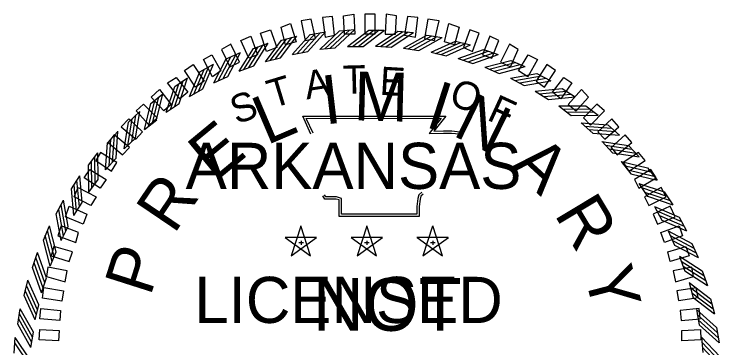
# Model space of a CAD drawing. Extents: x 16 to 1228743, y 11 to 152440.
# Drawn here: x 17.6797 to 17.8514, y 10.9098 to 10.9908 of the extents above; entities that cross this region are included whole.
import ezdxf

# ---------------------------------------------------------------- set-up
doc = ezdxf.new("R2010")
doc.units = 0
doc.layers.add('STAMP_JUSTIN', color=7, linetype='Continuous')
doc.layers.add('STAMP_PRELIM', color=7, linetype='Continuous')

msp = doc.modelspace()

# ---------------------------------------------------------------- linework, layer by layer
at = {"layer": 'STAMP_JUSTIN'}
for p, q in [((17.75872, 10.98673), (17.76248, 10.98708)), ((17.74471, 10.98447), (17.74835, 10.98543)), ((17.75167, 10.98589), (17.75538, 10.98654)), ((17.76586, 10.98694), (17.76963, 10.98694)), ((17.77292, 10.98666), (17.77668, 10.98638)), ((17.77997, 10.98574), (17.7837, 10.98516)), ((17.73788, 10.98247), (17.74144, 10.98373)), ((17.78692, 10.98425), (17.79058, 10.98336)), ((17.75397, 10.98227), (17.75773, 10.98261)), ((17.76072, 10.98293), (17.7645, 10.98293)), ((17.7675, 10.98304), (17.77127, 10.98276)), ((17.77427, 10.98258), (17.778, 10.98199)), ((17.79372, 10.98219), (17.7973, 10.981)), ((17.73125, 10.97992), (17.73469, 10.98147)), ((17.74075, 10.97928), (17.74441, 10.98024)), ((17.7473, 10.98105), (17.75102, 10.9817)), ((17.78097, 10.98157), (17.78464, 10.98068)), ((17.72485, 10.97684), (17.72815, 10.97866)), ((17.78757, 10.98001), (17.79116, 10.97881)), ((17.80033, 10.97957), (17.80379, 10.97809)), ((17.73437, 10.97698), (17.73793, 10.97824)), ((17.79402, 10.97791), (17.79749, 10.97642)), ((17.71873, 10.97323), (17.72186, 10.97532)), ((17.7282, 10.97416), (17.73165, 10.97571)), ((17.80027, 10.97528), (17.80361, 10.97351)), ((17.8067, 10.97642), (17.81003, 10.97465)), ((17.72229, 10.97084), (17.7256, 10.97266)), ((17.80629, 10.97214), (17.80947, 10.97011)), ((17.81278, 10.97275), (17.81596, 10.97072)), ((17.71292, 10.96913), (17.71588, 10.97147)), ((17.71667, 10.96704), (17.71982, 10.96913)), ((17.81202, 10.96852), (17.81502, 10.96623)), ((17.81854, 10.96859), (17.82154, 10.9663)), ((17.70748, 10.96456), (17.71023, 10.96714)), ((17.71139, 10.96279), (17.71435, 10.96514)), ((17.81744, 10.96444), (17.82024, 10.96191)), ((17.82394, 10.96397), (17.82674, 10.96144)), ((17.70243, 10.95957), (17.70495, 10.96236)), ((17.70647, 10.95812), (17.70923, 10.9607)), ((17.8225, 10.95993), (17.82508, 10.95717)), ((17.82894, 10.95892), (17.83152, 10.95617)), ((17.69781, 10.95417), (17.70009, 10.95716)), ((17.70195, 10.95306), (17.70449, 10.95586)), ((17.82717, 10.95501), (17.82952, 10.95205)), ((17.83351, 10.95347), (17.83585, 10.95052)), ((17.69365, 10.9484), (17.69568, 10.95158)), ((17.69787, 10.94764), (17.70017, 10.95065)), ((17.83142, 10.94972), (17.83351, 10.94658)), ((17.83761, 10.94767), (17.8397, 10.94453)), ((17.68998, 10.94232), (17.69174, 10.94565)), ((17.69425, 10.94191), (17.69629, 10.94509)), ((17.83521, 10.94411), (17.83704, 10.9408)), ((17.84121, 10.94155), (17.84304, 10.93825)), ((17.68683, 10.93595), (17.68831, 10.93942)), ((17.69112, 10.93589), (17.69289, 10.93923)), ((17.74939, 10.93938), (17.74703, 10.93214)), ((17.75174, 10.93215), (17.74939, 10.93939)), ((17.76538, 10.93938), (17.76302, 10.93214)), ((17.76773, 10.93215), (17.76539, 10.93939)), ((17.78137, 10.93938), (17.77901, 10.93214)), ((17.78372, 10.93215), (17.78138, 10.93939)), ((17.83853, 10.93819), (17.84008, 10.93475)), ((17.75319, 10.93661), (17.74558, 10.93662)), ((17.74559, 10.93661), (17.75174, 10.93214)), ((17.74704, 10.93215), (17.7532, 10.93661)), ((17.7494, 10.93581), (17.7494, 10.93485)), ((17.76918, 10.93661), (17.76157, 10.93662)), ((17.76158, 10.93661), (17.76773, 10.93214)), ((17.76303, 10.93215), (17.76919, 10.93661)), ((17.76539, 10.93581), (17.76539, 10.93485)), ((17.78517, 10.93661), (17.77756, 10.93662)), ((17.77757, 10.93661), (17.78372, 10.93214)), ((17.77902, 10.93215), (17.78518, 10.93661)), ((17.78138, 10.93581), (17.78138, 10.93485)), ((17.74885, 10.9354), (17.74998, 10.9354)), ((17.76484, 10.9354), (17.76597, 10.9354)), ((17.78083, 10.9354), (17.78196, 10.9354)), ((17.8443, 10.93515), (17.84585, 10.93171)), ((17.68421, 10.92934), (17.6854, 10.93292)), ((17.68849, 10.92964), (17.68998, 10.93312)), ((17.84135, 10.93202), (17.84261, 10.92846)), ((17.84685, 10.92851), (17.84811, 10.92496)), ((17.68215, 10.92254), (17.68304, 10.9262)), ((17.68639, 10.92319), (17.68758, 10.92678)), ((17.84366, 10.92565), (17.84462, 10.92199)), ((17.68483, 10.91659), (17.68572, 10.92027)), ((17.84884, 10.92169), (17.8498, 10.91805)), ((17.68065, 10.91559), (17.68124, 10.91932)), ((17.84542, 10.9191), (17.84608, 10.91538)), ((17.68381, 10.90989), (17.6844, 10.91362)), ((17.85027, 10.91473), (17.85092, 10.91102)), ((17.67974, 10.90855), (17.68001, 10.91231)), ((17.84664, 10.91243), (17.84699, 10.90866))]:
    msp.add_line(p, q, dxfattribs=at)
for points in [[(17.75773, 10.98261), (17.76248, 10.98708)], [(17.7444, 10.98024), (17.74835, 10.98543)], [(17.74729, 10.98104), (17.75166, 10.98588)], [(17.74849, 10.98124), (17.75286, 10.98608)], [(17.74978, 10.9815), (17.75415, 10.98634)], [(17.75102, 10.9817), (17.75538, 10.98655)], [(17.75397, 10.98226), (17.75872, 10.98673)], [(17.75517, 10.98236), (17.75993, 10.98683)], [(17.75648, 10.98251), (17.76123, 10.98698)], [(17.76071, 10.98293), (17.76586, 10.98694)], [(17.76193, 10.98292), (17.76707, 10.98693)], [(17.76324, 10.98295), (17.76838, 10.98696)], [(17.76449, 10.98293), (17.76964, 10.98695)], [(17.76749, 10.98303), (17.77292, 10.98666)], [(17.7687, 10.98293), (17.77413, 10.98656)], [(17.77001, 10.98287), (17.77544, 10.98649)], [(17.77126, 10.98276), (17.77669, 10.98639)], [(17.77426, 10.98258), (17.77997, 10.98574)], [(17.77546, 10.98238), (17.78116, 10.98554)], [(17.77676, 10.9822), (17.78246, 10.98537)], [(17.73793, 10.97824), (17.74144, 10.98373)], [(17.74075, 10.97927), (17.7447, 10.98446)], [(17.74192, 10.97957), (17.74588, 10.98476)], [(17.74318, 10.97993), (17.74714, 10.98512)], [(17.778, 10.982), (17.7837, 10.98516)], [(17.78097, 10.98157), (17.78691, 10.98425)], [(17.78214, 10.98127), (17.78809, 10.98395)], [(17.78342, 10.98099), (17.78937, 10.98367)], [(17.73437, 10.97697), (17.73788, 10.98247)], [(17.73552, 10.97737), (17.73903, 10.98286)], [(17.73674, 10.97783), (17.74025, 10.98333)], [(17.78464, 10.98068), (17.79059, 10.98336)], [(17.78757, 10.98001), (17.79371, 10.98219)], [(17.72931, 10.97464), (17.73236, 10.98041)], [(17.7305, 10.9752), (17.73354, 10.98097)], [(17.73165, 10.97571), (17.73469, 10.98147)], [(17.78871, 10.97961), (17.79486, 10.98179)], [(17.78997, 10.97923), (17.79611, 10.98141)], [(17.79115, 10.97882), (17.7973, 10.981)], [(17.72559, 10.97266), (17.72815, 10.97866)], [(17.7282, 10.97415), (17.73125, 10.97992)], [(17.79401, 10.9779), (17.80032, 10.97957)], [(17.79513, 10.97742), (17.80143, 10.97908)], [(17.79634, 10.97693), (17.80265, 10.97859)], [(17.72229, 10.97083), (17.72485, 10.97683)], [(17.72336, 10.97141), (17.72592, 10.97741)], [(17.72449, 10.97207), (17.72705, 10.97807)], [(17.79749, 10.97642), (17.8038, 10.97809)], [(17.71981, 10.96913), (17.72187, 10.97532)], [(17.80027, 10.97528), (17.80669, 10.97642)], [(17.80133, 10.9747), (17.80776, 10.97584)], [(17.8025, 10.97411), (17.80893, 10.97525)], [(17.71769, 10.9677), (17.71974, 10.97389)], [(17.71876, 10.96845), (17.72081, 10.97464)], [(17.80361, 10.97352), (17.81003, 10.97466)], [(17.71667, 10.96703), (17.71873, 10.97322)], [(17.80628, 10.97214), (17.81278, 10.97275)], [(17.8073, 10.97148), (17.81379, 10.97209)], [(17.71234, 10.96353), (17.71388, 10.96987)], [(17.71335, 10.96437), (17.71489, 10.97071)], [(17.71434, 10.96514), (17.71588, 10.97148)], [(17.80841, 10.9708), (17.81491, 10.9714)], [(17.80947, 10.97011), (17.81596, 10.97072)], [(17.71138, 10.96278), (17.71292, 10.96912)], [(17.81201, 10.96852), (17.81854, 10.96859)], [(17.70922, 10.9607), (17.71023, 10.96715)], [(17.81297, 10.96778), (17.81949, 10.96785)], [(17.81403, 10.96701), (17.82055, 10.96707)], [(17.70736, 10.95894), (17.70837, 10.96538)], [(17.7083, 10.95985), (17.7093, 10.9663)], [(17.75182, 10.96171), (17.74981, 10.96606), (17.78458, 10.96608), (17.78167, 10.96243), (17.78403, 10.96246), (17.78601, 10.96249), (17.78798, 10.96227)], [(17.75232, 10.96194), (17.75067, 10.96551), (17.78343, 10.96553), (17.78052, 10.96187), (17.78404, 10.96191), (17.78598, 10.96194), (17.78792, 10.96173)], [(17.81502, 10.96624), (17.82154, 10.9663)], [(17.70647, 10.95811), (17.70748, 10.96456)], [(17.81743, 10.96444), (17.82394, 10.96397)], [(17.81832, 10.96362), (17.82483, 10.96315)], [(17.70363, 10.95494), (17.7041, 10.96144)], [(17.70448, 10.95586), (17.70495, 10.96237)], [(17.81931, 10.96277), (17.82582, 10.96229)], [(17.82024, 10.96191), (17.82674, 10.96144)], [(17.70195, 10.95305), (17.70243, 10.95956)], [(17.70278, 10.95395), (17.70325, 10.96045)], [(17.82249, 10.95993), (17.82894, 10.95892)], [(17.82331, 10.95904), (17.82976, 10.95803)], [(17.82423, 10.9581), (17.83067, 10.95709)], [(17.69939, 10.94965), (17.69932, 10.95618)], [(17.70016, 10.95064), (17.70009, 10.95717)], [(17.82508, 10.95718), (17.83153, 10.95617)], [(17.69862, 10.94859), (17.69855, 10.95512)], [(17.82716, 10.95501), (17.8335, 10.95348)], [(17.69787, 10.94764), (17.69781, 10.95416)], [(17.82791, 10.95405), (17.83425, 10.95252)], [(17.82874, 10.95305), (17.83508, 10.95151)], [(17.69628, 10.94509), (17.69568, 10.95158)], [(17.82951, 10.95206), (17.83585, 10.95052)], [(17.69492, 10.94292), (17.69431, 10.94941)], [(17.6956, 10.94404), (17.69499, 10.95053)], [(17.83141, 10.94973), (17.8376, 10.94767)], [(17.69425, 10.9419), (17.69365, 10.9484)], [(17.77875, 10.94757), (17.77802, 10.94697), (17.77777, 10.94604), (17.77756, 10.94416), (17.77756, 10.94228), (17.75925, 10.94228), (17.75925, 10.94498), (17.75925, 10.9461), (17.758, 10.94649), (17.75545, 10.94649), (17.75512, 10.94699)], [(17.83207, 10.94871), (17.83826, 10.94666)], [(17.83282, 10.94764), (17.83902, 10.94558)], [(17.7791, 10.94714), (17.77851, 10.94666), (17.77831, 10.94594), (17.77811, 10.94413), (17.77811, 10.94173), (17.7587, 10.94173), (17.7587, 10.94498), (17.7587, 10.9457), (17.75792, 10.94594), (17.75515, 10.94594), (17.75466, 10.94669)], [(17.83351, 10.94659), (17.8397, 10.94453)], [(17.69228, 10.93813), (17.69114, 10.94455)], [(17.69288, 10.93923), (17.69174, 10.94565)], [(17.83521, 10.94411), (17.84121, 10.94155)], [(17.6917, 10.93696), (17.69056, 10.94338)], [(17.83579, 10.94304), (17.84179, 10.94048)], [(17.69112, 10.93589), (17.68998, 10.94231)], [(17.83644, 10.94191), (17.84244, 10.93935)], [(17.83704, 10.9408), (17.84304, 10.93825)], [(17.68997, 10.93311), (17.68831, 10.93942)], [(17.68947, 10.93196), (17.6878, 10.93827)], [(17.83853, 10.9382), (17.8443, 10.93515)], [(17.68849, 10.92964), (17.68683, 10.93594)], [(17.68898, 10.93075), (17.68731, 10.93705)], [(17.83902, 10.93708), (17.84478, 10.93404)], [(17.83958, 10.9359), (17.84535, 10.93286)], [(17.84008, 10.93475), (17.84585, 10.93171)], [(17.68758, 10.92678), (17.6854, 10.93292)], [(17.68678, 10.92434), (17.6846, 10.93048)], [(17.68717, 10.92559), (17.68499, 10.93174)], [(17.84135, 10.93203), (17.84685, 10.92852)], [(17.84174, 10.93088), (17.84724, 10.92737)], [(17.68639, 10.92319), (17.68421, 10.92934)], [(17.84221, 10.92966), (17.8477, 10.92614)], [(17.84262, 10.92847), (17.84811, 10.92496)], [(17.68572, 10.92026), (17.68304, 10.92621)], [(17.84365, 10.92565), (17.84884, 10.9217)], [(17.68513, 10.91777), (17.68245, 10.92371)], [(17.68541, 10.91904), (17.68273, 10.92499)], [(17.84395, 10.92447), (17.84914, 10.92052)], [(17.68483, 10.91659), (17.68215, 10.92254)], [(17.84431, 10.92321), (17.8495, 10.91926)], [(17.84462, 10.922), (17.84981, 10.91804)], [(17.6844, 10.91362), (17.68124, 10.91932)], [(17.84542, 10.9191), (17.85026, 10.91473)], [(17.68402, 10.91108), (17.68085, 10.91679)], [(17.68419, 10.91238), (17.68103, 10.91808)], [(17.84562, 10.91791), (17.85046, 10.91354)], [(17.68382, 10.90988), (17.68065, 10.91559)], [(17.84587, 10.91662), (17.85072, 10.91225)], [(17.84608, 10.91538), (17.85093, 10.91101)], [(17.68363, 10.90689), (17.68001, 10.91231)], [(17.84664, 10.91243), (17.85111, 10.90768)], [(17.68353, 10.90563), (17.67991, 10.91106)], [(17.84674, 10.91122), (17.85121, 10.90647)], [(17.84689, 10.90992), (17.85136, 10.90517)]]:
    msp.add_lwpolyline(points, dxfattribs=at)
at = {"layer": 'STAMP_PRELIM'}
for p, q in [((17.75975, 10.99043), (17.76225, 10.9908)), ((17.76, 10.98593), (17.75975, 10.99043)), ((17.76225, 10.9908), (17.76244, 10.98593)), ((17.76744, 10.9908), (17.76487, 10.9908)), ((17.76487, 10.9908), (17.76487, 10.98605)), ((17.76744, 10.98605), (17.76744, 10.9908)), ((17.77006, 10.9908), (17.76987, 10.98593)), ((17.77262, 10.99043), (17.77006, 10.9908)), ((17.77237, 10.98593), (17.77262, 10.99043)), ((17.75187, 10.98962), (17.74944, 10.98918)), ((17.74944, 10.98918), (17.75037, 10.98443)), ((17.75294, 10.98487), (17.75187, 10.98962)), ((17.75706, 10.99025), (17.75462, 10.99)), ((17.75462, 10.99), (17.75525, 10.98525)), ((17.75756, 10.98568), (17.75706, 10.99025)), ((17.77525, 10.99025), (17.7745, 10.98568)), ((17.77775, 10.99), (17.77525, 10.99025)), ((17.77719, 10.98525), (17.77775, 10.99)), ((17.78019, 10.98962), (17.77937, 10.98487)), ((17.78294, 10.98918), (17.78019, 10.98962)), ((17.78181, 10.98443), (17.78294, 10.98918)), ((17.74456, 10.98768), (17.74687, 10.9885)), ((17.74562, 10.98337), (17.74456, 10.98768)), ((17.74687, 10.9885), (17.74825, 10.98405)), ((17.78425, 10.98405), (17.78531, 10.9885)), ((17.78531, 10.9885), (17.78781, 10.98768)), ((17.78781, 10.98768), (17.78669, 10.98337)), ((17.73475, 10.98443), (17.73719, 10.9855)), ((17.73719, 10.9855), (17.73881, 10.98093)), ((17.73956, 10.98618), (17.742, 10.987)), ((17.74106, 10.98175), (17.73956, 10.98618)), ((17.742, 10.987), (17.7435, 10.98268)), ((17.75525, 10.98525), (17.75756, 10.98568)), ((17.76244, 10.98593), (17.76, 10.98593)), ((17.76487, 10.98605), (17.76744, 10.98605)), ((17.76987, 10.98593), (17.77237, 10.98593)), ((17.7745, 10.98568), (17.77719, 10.98525)), ((17.79037, 10.987), (17.78887, 10.98268)), ((17.79269, 10.98618), (17.79037, 10.987)), ((17.79106, 10.98175), (17.79269, 10.98618)), ((17.79525, 10.9855), (17.7935, 10.98093)), ((17.79744, 10.98443), (17.79525, 10.9855)), ((17.73669, 10.98012), (17.73475, 10.98443)), ((17.74825, 10.98405), (17.74562, 10.98337)), ((17.75037, 10.98443), (17.75294, 10.98487)), ((17.77937, 10.98487), (17.78181, 10.98443)), ((17.78669, 10.98337), (17.78425, 10.98405)), ((17.79575, 10.98012), (17.79744, 10.98443)), ((17.73237, 10.9835), (17.73006, 10.98225)), ((17.73006, 10.98225), (17.73212, 10.97805)), ((17.73444, 10.97918), (17.73237, 10.9835)), ((17.7435, 10.98268), (17.74106, 10.98175)), ((17.78887, 10.98268), (17.79106, 10.98175)), ((17.8, 10.9835), (17.79787, 10.97918)), ((17.80212, 10.98225), (17.8, 10.9835)), ((17.80025, 10.97805), (17.80212, 10.98225)), ((17.72575, 10.9798), (17.72775, 10.98093)), ((17.72775, 10.98093), (17.72994, 10.97705)), ((17.73881, 10.98093), (17.73669, 10.98012)), ((17.7935, 10.98093), (17.79575, 10.98012)), ((17.80225, 10.97705), (17.80456, 10.98093)), ((17.80456, 10.98093), (17.80681, 10.9798)), ((17.72112, 10.97712), (17.72319, 10.97862)), ((17.72319, 10.97862), (17.72587, 10.97455)), ((17.72787, 10.97562), (17.72575, 10.9798)), ((17.73212, 10.97805), (17.73444, 10.97918)), ((17.79787, 10.97918), (17.80025, 10.97805)), ((17.80681, 10.9798), (17.8045, 10.97562)), ((17.80906, 10.97862), (17.8065, 10.97455)), ((17.81119, 10.97712), (17.80906, 10.97862)), ((17.72381, 10.97305), (17.72112, 10.97712)), ((17.72994, 10.97705), (17.72787, 10.97562)), ((17.8045, 10.97562), (17.80225, 10.97705)), ((17.80856, 10.97305), (17.81119, 10.97712)), ((17.717, 10.97412), (17.71912, 10.97543)), ((17.71912, 10.97543), (17.72194, 10.97187)), ((17.81044, 10.97187), (17.81319, 10.97543)), ((17.81319, 10.97543), (17.81519, 10.97412)), ((17.71994, 10.97025), (17.717, 10.97412)), ((17.72587, 10.97455), (17.72381, 10.97305)), ((17.8065, 10.97455), (17.80856, 10.97305)), ((17.81519, 10.97412), (17.8125, 10.97025)), ((17.713, 10.97062), (17.71506, 10.9725)), ((17.71506, 10.9725), (17.71787, 10.96887)), ((17.72194, 10.97187), (17.71994, 10.97025)), ((17.8125, 10.97025), (17.81044, 10.97187)), ((17.8175, 10.9725), (17.81431, 10.96887)), ((17.81925, 10.97062), (17.8175, 10.9725)), ((17.71606, 10.9673), (17.713, 10.97062)), ((17.81625, 10.9673), (17.81925, 10.97062)), ((17.70937, 10.9673), (17.71112, 10.96893)), ((17.71112, 10.96893), (17.71444, 10.96568)), ((17.71787, 10.96887), (17.71606, 10.9673)), ((17.81431, 10.96887), (17.81625, 10.9673)), ((17.82125, 10.96893), (17.818, 10.96568)), ((17.82306, 10.9673), (17.82125, 10.96893)), ((17.7125, 10.96387), (17.70937, 10.9673)), ((17.81969, 10.96387), (17.82306, 10.9673)), ((17.70756, 10.96537), (17.70569, 10.96343)), ((17.71094, 10.96225), (17.70756, 10.96537)), ((17.71444, 10.96568), (17.7125, 10.96387)), ((17.818, 10.96568), (17.81969, 10.96387)), ((17.82487, 10.96537), (17.82144, 10.96225)), ((17.82656, 10.96343), (17.82487, 10.96537)), ((17.70569, 10.96343), (17.70931, 10.96043)), ((17.82319, 10.96043), (17.82656, 10.96343)), ((17.70406, 10.96155), (17.70256, 10.95962)), ((17.70775, 10.95843), (17.70406, 10.96155)), ((17.70931, 10.96043), (17.71094, 10.96225)), ((17.82144, 10.96225), (17.82319, 10.96043)), ((17.82812, 10.96155), (17.82469, 10.95843)), ((17.82975, 10.95962), (17.82812, 10.96155)), ((17.70256, 10.95962), (17.70606, 10.95668)), ((17.82619, 10.95668), (17.82975, 10.95962)), ((17.70606, 10.95668), (17.70775, 10.95843)), ((17.82469, 10.95843), (17.82619, 10.95668)), ((17.70075, 10.95725), (17.69956, 10.9553)), ((17.70469, 10.9548), (17.70075, 10.95725)), ((17.83137, 10.95725), (17.82762, 10.9548)), ((17.83294, 10.9553), (17.83137, 10.95725)), ((17.69956, 10.9553), (17.70337, 10.95268)), ((17.70337, 10.95268), (17.70469, 10.9548)), ((17.82762, 10.9548), (17.829, 10.95268)), ((17.829, 10.95268), (17.83294, 10.9553)), ((17.69675, 10.95105), (17.69812, 10.95312)), ((17.69812, 10.95312), (17.70206, 10.95068)), ((17.83431, 10.95312), (17.83037, 10.95068)), ((17.83562, 10.95105), (17.83431, 10.95312)), ((17.70062, 10.94855), (17.69675, 10.95105)), ((17.83144, 10.94855), (17.83562, 10.95105)), ((17.70206, 10.95068), (17.70062, 10.94855)), ((17.83037, 10.95068), (17.83144, 10.94855)), ((17.69431, 10.9465), (17.69525, 10.94875)), ((17.69525, 10.94875), (17.69962, 10.9465)), ((17.83687, 10.94875), (17.83281, 10.9465)), ((17.83806, 10.9465), (17.83687, 10.94875)), ((17.69837, 10.94437), (17.69431, 10.9465)), ((17.69962, 10.9465), (17.69837, 10.94437)), ((17.83281, 10.9465), (17.83387, 10.94437)), ((17.83387, 10.94437), (17.83806, 10.9465)), ((17.69225, 10.94162), (17.69312, 10.94418)), ((17.69312, 10.94418), (17.69737, 10.94225)), ((17.83906, 10.94418), (17.83494, 10.94225)), ((17.84025, 10.94162), (17.83906, 10.94418)), ((17.6965, 10.93987), (17.69225, 10.94162)), ((17.69737, 10.94225), (17.6965, 10.93987)), ((17.83494, 10.94225), (17.83594, 10.93987)), ((17.83594, 10.93987), (17.84025, 10.94162)), ((17.69119, 10.93943), (17.69031, 10.937)), ((17.69537, 10.9378), (17.69119, 10.93943)), ((17.83675, 10.9378), (17.84119, 10.93943)), ((17.84119, 10.93943), (17.842, 10.937)), ((17.69469, 10.93537), (17.69537, 10.9378)), ((17.83769, 10.93537), (17.83675, 10.9378)), ((17.69031, 10.937), (17.69469, 10.93537)), ((17.842, 10.937), (17.83769, 10.93537)), ((17.68937, 10.93443), (17.68869, 10.93218)), ((17.69387, 10.93312), (17.68937, 10.93443)), ((17.8385, 10.93312), (17.84281, 10.93443)), ((17.84281, 10.93443), (17.84362, 10.93218)), ((17.68869, 10.93218), (17.69312, 10.93075)), ((17.69312, 10.93075), (17.69387, 10.93312)), ((17.83906, 10.93075), (17.8385, 10.93312)), ((17.84362, 10.93218), (17.83906, 10.93075)), ((17.68794, 10.92943), (17.68756, 10.92712)), ((17.69262, 10.9285), (17.68794, 10.92943)), ((17.84431, 10.92943), (17.83981, 10.9285)), ((17.84469, 10.92712), (17.84431, 10.92943)), ((17.68756, 10.92712), (17.69212, 10.92587)), ((17.69212, 10.92587), (17.69262, 10.9285)), ((17.83981, 10.9285), (17.84031, 10.92587)), ((17.84031, 10.92587), (17.84469, 10.92712)), ((17.68662, 10.92187), (17.68694, 10.92443)), ((17.68694, 10.92443), (17.69169, 10.92362)), ((17.69169, 10.92362), (17.69131, 10.92118)), ((17.84537, 10.92437), (17.84069, 10.92368)), ((17.84069, 10.92368), (17.84106, 10.9213)), ((17.84581, 10.92205), (17.84537, 10.92437)), ((17.69131, 10.92118), (17.68662, 10.92187)), ((17.84106, 10.9213), (17.84581, 10.92205)), ((17.686, 10.91687), (17.68625, 10.91937)), ((17.68625, 10.91937), (17.691, 10.91887)), ((17.691, 10.91887), (17.69081, 10.91643)), ((17.84606, 10.91937), (17.8415, 10.91887)), ((17.8415, 10.91887), (17.84175, 10.91643)), ((17.84631, 10.91687), (17.84606, 10.91937)), ((17.69081, 10.91643), (17.686, 10.91687)), ((17.84175, 10.91643), (17.84631, 10.91687)), ((17.68581, 10.9118), (17.68594, 10.91425)), ((17.68594, 10.91425), (17.69069, 10.914)), ((17.69069, 10.914), (17.6905, 10.91155)), ((17.84187, 10.914), (17.84637, 10.91425)), ((17.84187, 10.91155), (17.84187, 10.914)), ((17.84637, 10.91425), (17.8465, 10.9118)), ((17.6905, 10.91155), (17.68581, 10.9118)), ((17.8465, 10.9118), (17.84187, 10.91155))]:
    msp.add_line(p, q, dxfattribs=at)

# ---------------------------------------------------------------- texts
at = {"layer": 'STAMP_JUSTIN'}
for s, rotation, p in [('T', 1.4789, (17.75961, 10.97145)), ('A', 8.6788, (17.75076, 10.97008)), ('E', 356.672, (17.76839, 10.97124)), ('T', 16.9015, (17.74243, 10.96791)), ('O', 341.2218, (17.78504, 10.96889)), ('S', 19.7726, (17.73371, 10.96399)), ('F', 335.3628, (17.79429, 10.96527))]:
    msp.add_text(s, height=0.00686, rotation=rotation, dxfattribs=at).set_placement(p)
for s, p in [('ARKANSAS', (17.72139, 10.94839)), ('LICENSED', (17.72352, 10.91586))]:
    msp.add_text(s, height=0.011194, dxfattribs=at).set_placement(p)
at = {"layer": 'STAMP_PRELIM'}
for s, rotation, p in [('M', 358.4667, (17.76212, 10.96505)), ('I', 6.6752, (17.75519, 10.964)), ('I', 342.0495, (17.77925, 10.96355)), ('N', 333.841, (17.78594, 10.9615)), ('L', 23.0924, (17.74106, 10.95893)), ('E', 39.5095, (17.72844, 10.94987)), ('A', 317.4238, (17.79994, 10.95355)), ('R', 55.9266, (17.71856, 10.93718)), ('R', 301.0067, (17.81075, 10.9423)), ('P', 72.3438, (17.71281, 10.92212)), ('Y', 284.5896, (17.81806, 10.928))]:
    msp.add_text(s, height=0.01184, rotation=rotation, dxfattribs=at).set_placement(p)
msp.add_text('NOT', height=0.012794, dxfattribs=at).set_placement((17.75231, 10.91396))

doc.saveas('drawing.dxf')
